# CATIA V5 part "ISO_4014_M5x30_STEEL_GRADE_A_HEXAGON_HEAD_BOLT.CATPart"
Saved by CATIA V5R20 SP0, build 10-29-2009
Part number: ISO 4014 BOLT M5x30 STEEL GRADE A HEXAGON HEAD.6
Publications: "Mating Face", "Axis"
Bounding box of the stored display mesh (mm): x -30 to 3.65, y -4 to 4, z -4.619 to 4.619
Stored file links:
  E:\设计\180212313林恺昇\ISO_4014_M5x30_STEEL_GRADE_A_HEXAGON_HEAD_BOLT.CATPart
  d:\Dassault Systemes\B20\win_b64\startup\components\MechanicalStandardParts\EN_Standards\Design_Tables\EN_ISO_4014_GRADES_A_B_HEXAGON_HEAD_BOLT.txt
  C:\Program Files\Dassault Systemes\B20\intel_a\startup\components\MechanicalStandardParts\ISO_Standards\Design_Tables\ISO_4014_GRADES_A_B_HEXAGON_HEAD_BOLT.txt
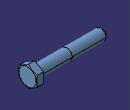
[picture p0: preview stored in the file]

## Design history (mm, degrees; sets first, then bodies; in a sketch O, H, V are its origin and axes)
Parameters
  d_dia = 5 mm
  l_length = 30 mm
  s_nom_across_flats = 8 mm
  k_max_head_depth = 3.65 mm
  dw_min = 6.88 mm
  r_min = 0.2 mm
  c_max = 0.5 mm
  p_pitch = 0.8 mm
  threading = 16 mm
Body1 "PartBody" (main body)
  Sketch1 on yz-plane, origin (0, 0, 0), H (0, 1, 0), V (0, 0, 1)
    circle A1 centre (0, 0) radius 3.44
    radius A1 = 3.44 {= dw_min /2}
  Pad1: profile Sketch1, direction (1, 0, 0), length 0.5 {= c_max}
  Sketch2 on face of Pad1, origin (0.5, 0, 0), H (0, 1, 0), V (0, 0, 1)
    point P1 (4, -2.3094)
    point P2 (4, 2.3094)
    point P3 (0, 4.6188)
    point P4 (-4, 2.3094)
    point P5 (-4, -2.3094)
    point P6 (0, -4.6188)
    point P7 (4, 0)
    line L1 (4, -2.3094) -> (4, 2.3094)
    line L2 (4, 2.3094) -> (0, 4.6188)
    line L3 (0, 4.6188) -> (-4, 2.3094)
    line L4 (-4, 2.3094) -> (-4, -2.3094)
    line L5 (-4, -2.3094) -> (0, -4.6188)
    line L6 (0, -4.6188) -> (4, -2.3094)
    construction line L7 (0, 0) -> (4, 0)
    construction circle A1 centre (0, 0) radius 4.6188
    construction arc A2 centre (-4, -2.3094) radius 4.6188 from (-4, 2.3094) to (0, -4.6188) cw
    construction arc A3 centre (4, 2.3094) radius 4.6188 from (0, 4.6188) to (4, -2.3094) ccw
    point P8 (-4, -2.3094)
    point P9 (4, 2.3094)
    distance L1 L4 = 8 {= s_nom_across_flats}
    horizontal: L7 H
    coincidence: A1 P1, A1 P2, A1 P3, A1 P4, A1 P5, A1 P6, A2 P4, A2 P6, A2 O, P8 P5, A3 P3, A3 P1, A3 O, P9 P2
    midpoint: P7 L1
  Pad2: profile Sketch2, direction (1, 0, 0), length 3.15 {= k_max_head_depth -c_max}
  Sketch3 on zx-plane, origin (0, 0, 0), H (-1, 0, 0), V (0, 0, 1)
    point P1 (-3.65, 3.9821)
    axis line L1 (-94.6904, 0) -> (76.7146, 0)
    reference intersected line E1 through (1000000, 0) direction (-1, 0) from xy-plane
    line L2 (-3.2824, 4.6188) -> (-3.65, 3.9821)
    line L3 (-3.2824, 4.6188) -> (-3.65, 4.6188)
    line L4 (-3.65, 4.6188) -> (-3.65, 3.9821)
    reference projected line E2 (-0.8, 4.6188) -> (-18.28, 4.6188) from edge [face of Pad2 | face of Pad2]
    distance P1 H = 3.9821 {= s_nom_across_flats /2.009}
    distance P1 V = 3.65 {= k_max_head_depth}
    angle L4 L2 = 30
    horizontal: L1 H, L3 H
    coincidence: L1 E1, L3 E2
    vertical: L4 V
  Groove1: profile Sketch3, axis Sketch3.L1, angle 360
  Sketch4 on face of Pad1, origin (0, 0, 0), H (0, -1, 0), V (0, 0, 1)
    circle A1 centre (0, 0) radius 2.5
    radius A1 = 2.5 {= d_dia /2}
  Pad3: profile Sketch4, direction (-1, 0, 0), length 14 {= l_length -threading}
  Sketch5 on face of Pad3, origin (-14, 0, 0), H (0, -1, 0), V (0, 0, 1)
    circle A1 centre (0, 0) radius 2.439
    radius A1 = 2.439 {= d_dia /2.05}
  Pad4: profile Sketch5, direction (-1, 0, 0), length 16 {= threading}
  Chamfer1: length 0.8 {= p_pitch}, angle 45, on face of Pad4
  Fillet1: radius 0.2 {= r_min}, on edge [face of Pad3 | face of Pad1]
  Thread1: diameter 4.878 {= d_dia /1.025}, depth 16 {= threading}, pitch 1, on face of Pad4, from face of Pad4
